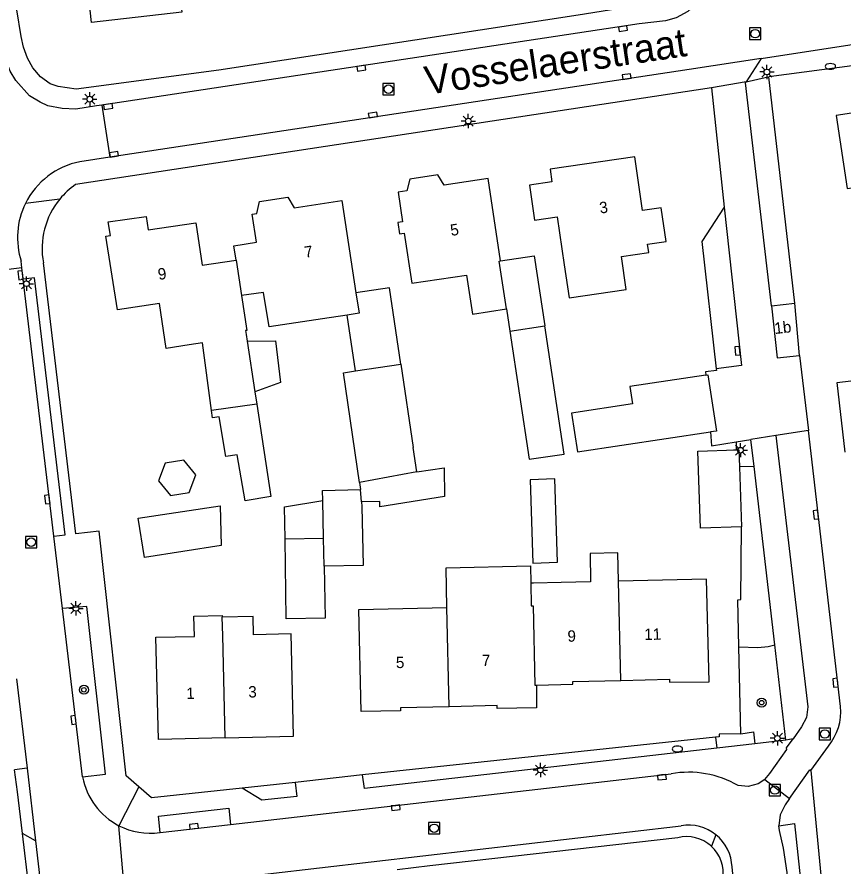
# Model space of a CAD drawing. Extents: x 140000 to 143000, y 403500 to 406000.
# Drawn here: x 140434.8 to 140507.5, y 403776.7 to 403851.4 of the extents above; entities that cross this region are included whole.
import ezdxf

# ---------------------------------------------------------------- set-up
doc = ezdxf.new("R2010")
doc.units = 0
for name, color, linetype in [('gg-afsc-erfafscheiding', 7, 'Continuous'), ('gg-anno-huisnummerreeks BGT', 7, 'Continuous'), ('gg-anno-openbare ruimte label', 7, 'Continuous'), ('gg-bbg-bijgebouw', 7, 'Continuous'), ('gg-bbg-gedigitaliseerde bebouwing', 7, 'Continuous'), ('gg-bbg-gedigitaliseerde bijgebouw', 7, 'Continuous'), ('gg-bbg-hoofdgebouw', 7, 'Continuous'), ('gg-bbg-luifel en loopbrug', 7, 'Continuous'), ('gg-bbg-overig bouwwerk', 7, 'Continuous'), ('gg-bbg-tussenscheiding', 7, 'Continuous'), ('gg-knt-verharding', 7, 'Continuous'), ('gg-knt-verharding nz', 7, 'Continuous'), ('gt-grn-groengrens', 7, 'Continuous'), ('gt-grn-vlakafsluiter', 7, 'Continuous'), ('gt-grn-weggrens', 7, 'Continuous'), ('gt-symb-boom', 7, 'Continuous'), ('gt-symb-brandkraan', 7, 'Continuous'), ('gt-symb-kolk', 7, 'Continuous'), ('gt-symb-lichtmast', 7, 'Continuous'), ('gt-symb-rioolschacht', 7, 'Continuous')]:
    doc.layers.add(name, color=color, linetype=linetype)

# ---------------------------------------------------------------- blocks, each defined once
blk = doc.blocks.new('gt0-KOLK')
at = {"layer": 'gt-symb-kolk'}
blk.add_lwpolyline([(0, 0), (0.375, 0), (0.375, 0.4), (-0.375, 0.4), (-0.375, 0), (0, 0)], dxfattribs=at)
blk = doc.blocks.new('gt0-RS')
at = {"layer": 'gt-symb-rioolschacht'}
blk.add_lwpolyline([(-0.5, -0.5), (0.5, -0.5), (0.5, 0.5), (-0.5, 0.5)], close=True, dxfattribs=at)
blk.add_circle((0, 0), 0.375, dxfattribs=at)
blk = doc.blocks.new('gt0-LMAST')
at = {"layer": 'gt-symb-lichtmast'}
for p, q in [((-0.182, 0.173), (-0.447, 0.438)), ((-0.005, 0.246), (-0.005, 0.621)), ((0.172, 0.173), (0.437, 0.438)), ((-0.255, -0.004), (-0.63, -0.004)), ((-0.182, -0.181), (-0.447, -0.446)), ((-0.005, -0.254), (-0.005, -0.629)), ((0.437, -0.446), (0.172, -0.181)), ((0.245, -0.004), (0.62, -0.004))]:
    blk.add_line(p, q, dxfattribs=at)
blk.add_circle((-0.005, -0.004), 0.25, dxfattribs=at)
blk = doc.blocks.new('gt0-BOOM')
at = {"layer": 'gt-symb-boom'}
for radius in [0.4, 0.2]:
    blk.add_circle((0, 0), radius, dxfattribs=at)
blk = doc.blocks.new('gt0-BR')
at = {"layer": 'gt-symb-brandkraan'}
for centre, radius, start, end in [((-0.244, 0), 0.206, 107.56694, 252.43307), ((0.599, -2.664), 3, 106.89205, 107.56694), ((0, -0.691), 0.938, 73.10799, 106.89205), ((-0.599, -2.664), 3, 72.43309, 73.10799), ((0.244, 0), 0.206, 287.56695, 72.43309), ((0.599, 2.664), 3, 252.43307, 253.10797), ((0, 0.691), 0.938, 253.10797, 286.89206), ((-0.599, 2.664), 3, 286.89206, 287.56695)]:
    blk.add_arc(centre, radius, start, end, dxfattribs=at)

msp = doc.modelspace()

# ---------------------------------------------------------------- linework, layer by layer
at = {"layer": 'gg-afsc-erfafscheiding'}
for p, q in [((140503.231, 403826.221), (140500.938, 403846.136)), ((140492.932, 403779.221), (140471.115, 403776.739)), ((140471.115, 403776.739), (140468.236, 403776.411))]:
    msp.add_line(p, q, dxfattribs=at)
msp.add_arc((140493.716, 403776.097), 3.221, 47.69374, 104.08768, dxfattribs=at)
at = {"layer": 'gg-bbg-bijgebouw'}
for p, q in [((140478.15, 403823.755), (140481.22, 403824.22)), ((140464.589, 403820.269), (140468.559, 403820.85)), ((140468.559, 403820.85), (140469.642, 403813.549)), ((140469.962, 403811.391), (140469.642, 403813.549)), ((140498.076, 403813.323), (140498.3, 403813.33)), ((140498.3, 403813.33), (140498.351, 403811.833)), ((140498.351, 403811.833), (140498.53, 403806.572)), ((140461.76, 403805.569), (140461.695, 403808.881)), ((140458.384, 403805.5), (140461.76, 403805.569))]:
    msp.add_line(p, q, dxfattribs=at)
for points in [[(140478.15, 403823.755), (140479.857, 403812.498), (140482.928, 403812.964), (140481.22, 403824.22)], [(140464.933, 403810.456), (140463.52, 403820.112), (140464.589, 403820.269)], [(140495.404, 403819.9), (140492.045, 403819.386), (140488.717, 403818.896), (140488.942, 403817.368), (140483.589, 403816.556), (140484.099, 403813.143), (140495.811, 403814.905)], [(140495.404, 403819.9), (140495.584, 403819.928), (140496.341, 403814.986), (140495.811, 403814.905)], [(140498.53, 403806.572), (140494.93, 403806.45), (140494.7, 403813.21), (140498.076, 403813.323)], [(140480.182, 403803.367), (140482.349, 403803.44), (140482.102, 403810.768), (140479.935, 403810.695), (140480.182, 403803.367)], [(140461.695, 403808.881), (140461.677, 403809.765), (140465.025, 403809.831)], [(140465.107, 403808.773), (140465.139, 403808.352), (140465.243, 403803.165), (140461.811, 403803.096)], [(140446.006, 403803.855), (140445.464, 403807.318), (140452.663, 403808.404), (140452.755, 403804.911), (140446.006, 403803.855)], [(140461.811, 403803.096), (140461.902, 403798.537), (140458.488, 403798.468), (140458.384, 403805.5)]]:
    msp.add_lwpolyline(points, dxfattribs=at)
at = {"layer": 'gg-bbg-gedigitaliseerde bebouwing'}
msp.add_line((140464.858, 403799.306), (140472.622, 403799.466), dxfattribs=at)
msp.add_lwpolyline([(140472.622, 403799.466), (140472.55, 403802.965), (140479.97, 403803.117), (140480.001, 403801.616)], dxfattribs=at)
at = {"layer": 'gg-bbg-gedigitaliseerde bijgebouw'}
msp.add_line((140464.933, 403810.456), (140465.025, 403809.831), dxfattribs=at)
msp.add_lwpolyline([(140469.962, 403811.391), (140472.365, 403811.741), (140472.392, 403809.232), (140466.724, 403808.32), (140466.725, 403808.785), (140465.107, 403808.773)], dxfattribs=at)
at = {"layer": 'gg-bbg-hoofdgebouw'}
for p, q in [((140501.17, 403825.991), (140503.231, 403826.221)), ((140503.65, 403821.639), (140503.231, 403826.221)), ((140455.05, 403822.895), (140455.726, 403818.438)), ((140455.726, 403818.438), (140455.889, 403817.359)), ((140455.889, 403817.359), (140451.917, 403816.778))]:
    msp.add_line(p, q, dxfattribs=at)
for points in [[(140448.38, 403859.973), (140449.301, 403851.812), (140441.361, 403850.92), (140440.881, 403855.261), (140441.741, 403855.361), (140441.317, 403859.174)], [(140528.15, 403843.84), (140523.65, 403843.181), (140523.74, 403842.571), (140519.79, 403841.97), (140519.39, 403844.641), (140506.88, 403842.742), (140507.84, 403836.301), (140520.353, 403838.182), (140520.336, 403838.291), (140524.286, 403838.886), (140525.215, 403832.729), (140526.239, 403832.883), (140529.709, 403833.407), (140528.326, 403842.664)], [(140490.271, 403831.419), (140491.9, 403831.659), (140491.463, 403834.624), (140489.834, 403834.384), (140489.14, 403839.092), (140481.7, 403838.001), (140481.864, 403836.882), (140479.875, 403836.591), (140480.325, 403833.524), (140482.317, 403833.817), (140482.94, 403829.592), (140483.366, 403826.683), (140488.4, 403827.42), (140487.974, 403830.329), (140490.38, 403830.681), (140490.271, 403831.419)], [(140477.327, 403829.937), (140476.24, 403837.18), (140472.384, 403836.595), (140471.833, 403837.516), (140469.345, 403837.135), (140469.097, 403836.097), (140468.33, 403835.981), (140468.721, 403833.372), (140468.31, 403833.311), (140468.46, 403832.322), (140468.87, 403832.384), (140469.535, 403827.975), (140474.353, 403828.701), (140474.875, 403825.258), (140477.85, 403825.732)], [(140454.064, 403830.012), (140453.87, 403831.28), (140455.857, 403831.584), (140455.481, 403834.041), (140455.881, 403834.102), (140456.132, 403835.153), (140458.62, 403835.534), (140459.175, 403834.607), (140463.38, 403835.252), (140464.619, 403827.139)], [(140451.917, 403816.778), (140451.108, 403822.74), (140449.943, 403822.57), (140447.91, 403822.251), (140447.321, 403826.201), (140443.621, 403825.632), (140442.611, 403832.131), (140443.007, 403832.189), (140442.824, 403833.368), (140446.148, 403833.852), (140446.331, 403832.676), (140450.531, 403833.291), (140451.072, 403829.576), (140454.064, 403830.012)], [(140477.85, 403825.732), (140477.215, 403829.92), (140477.327, 403829.937)], [(140463.845, 403825.178), (140461.68, 403824.85), (140456.994, 403824.139), (140456.486, 403827.179), (140454.536, 403826.897)], [(140454.536, 403826.897), (140455, 403823.837), (140454.91, 403823.823), (140454.961, 403823.485), (140455.05, 403822.895)], [(140464.619, 403827.139), (140464.894, 403825.337), (140463.845, 403825.178)], [(140501.17, 403825.991), (140501.69, 403821.421), (140503.65, 403821.639)], [(140507.668, 403813.118), (140506.95, 403819.26), (140510.09, 403819.628)], [(140487.72, 403801.775), (140487.664, 403804.274), (140485.215, 403804.22), (140485.266, 403801.724), (140482.681, 403801.671), (140480.226, 403801.621), (140480.001, 403801.616)], [(140487.915, 403793.056), (140492.21, 403793.152), (140492.21, 403792.9), (140495.7, 403792.942), (140495.471, 403801.951), (140487.72, 403801.775)], [(140472.818, 403790.743), (140468.53, 403790.642), (140468.53, 403790.391), (140465.06, 403790.31), (140464.858, 403799.306)], [(140453.113, 403787.995), (140447.231, 403787.852), (140447.011, 403796.851), (140450.398, 403796.932), (140450.354, 403798.708), (140452.853, 403798.769), (140452.857, 403798.619)], [(140453.113, 403787.995), (140459.13, 403788.142), (140458.91, 403797.142), (140455.611, 403797.06), (140455.57, 403798.686), (140452.857, 403798.619)], [(140480.5, 403792.632), (140483.69, 403792.712), (140483.69, 403792.961), (140487.915, 403793.056)], [(140480.5, 403792.632), (140480.51, 403790.642), (140477.05, 403790.591), (140477.05, 403790.842), (140472.818, 403790.743)]]:
    msp.add_lwpolyline(points, dxfattribs=at)
at = {"layer": 'gg-bbg-luifel en loopbrug'}
for p, q in [((140464.589, 403820.269), (140463.845, 403825.178)), ((140477.85, 403825.732), (140478.15, 403823.755))]:
    msp.add_line(p, q, dxfattribs=at)
for points in [[(140477.327, 403829.937), (140480.285, 403830.386), (140481.22, 403824.22)], [(140468.559, 403820.85), (140467.561, 403827.576), (140464.619, 403827.139)], [(140455.05, 403822.895), (140457.53, 403822.929), (140457.982, 403819.257), (140455.726, 403818.438)], [(140458.384, 403805.5), (140458.327, 403808.311), (140461.695, 403808.881)]]:
    msp.add_lwpolyline(points, dxfattribs=at)
at = {"layer": 'gg-bbg-overig bouwwerk'}
for points in [[(140455.889, 403817.359), (140457.119, 403809.238), (140454.862, 403808.839), (140454.158, 403812.885), (140453.154, 403812.737), (140452.574, 403816.231), (140452.002, 403816.155), (140451.917, 403816.778)], [(140449.461, 403812.429), (140447.815, 403812.155), (140447.229, 403810.594), (140448.288, 403809.305), (140449.934, 403809.578), (140450.52, 403811.14), (140449.461, 403812.429)]]:
    msp.add_lwpolyline(points, dxfattribs=at)
at = {"layer": 'gg-bbg-tussenscheiding'}
for p, q in [((140454.064, 403830.012), (140454.536, 403826.897)), ((140469.962, 403811.391), (140464.933, 403810.456)), ((140465.107, 403808.773), (140465.025, 403809.831)), ((140461.811, 403803.096), (140461.76, 403805.569)), ((140480.001, 403801.616), (140480.043, 403799.618)), ((140487.915, 403793.056), (140487.72, 403801.775)), ((140472.818, 403790.743), (140472.622, 403799.466))]:
    msp.add_line(p, q, dxfattribs=at)
for points in [[(140480.043, 403799.618), (140480.194, 403799.621), (140480.35, 403792.628), (140480.5, 403792.632)], [(140453.113, 403787.995), (140452.897, 403796.992), (140452.857, 403798.619)]]:
    msp.add_lwpolyline(points, dxfattribs=at)
at = {"layer": 'gg-knt-verharding'}
for p, q in [((140500.27, 403847.752), (140562.382, 403857.344)), ((140500.27, 403847.752), (140498.958, 403845.701)), ((140498.958, 403845.701), (140495.89, 403845.171)), ((140495.89, 403845.171), (140439.951, 403836.65)), ((140495.89, 403845.171), (140497.025, 403834.669)), ((140442.265, 403843.641), (140442.959, 403839.06)), ((140442.959, 403839.06), (140440.331, 403838.662)), ((140438.565, 403835.385), (140435.538, 403834.993)), ((140435.228, 403829.329), (140435.158, 403829.915)), ((140435.228, 403829.329), (140430.557, 403828.746)), ((140435.347, 403828.329), (140435.228, 403829.329)), ((140438.041, 403805.734), (140435.347, 403828.329)), ((140503.65, 403821.639), (140504.421, 403815.028)), ((140501.57, 403814.58), (140499.368, 403814.234)), ((140507.25, 403790.771), (140504.421, 403815.028)), ((140498.069, 403814.03), (140499.368, 403814.234)), ((140499.642, 403811.877), (140499.368, 403814.234)), ((140501.463, 403796.199), (140499.642, 403811.877)), ((140438.798, 403799.381), (140438.041, 403805.734)), ((140440.562, 403784.579), (140438.798, 403799.381)), ((140498.485, 403788.356), (140498.309, 403796.01)), ((140502.44, 403787.791), (140501.463, 403796.199)), ((140434.747, 403793.2), (140435.674, 403785.339)), ((140496.255, 403788.056), (140496.366, 403787.094)), ((140502.44, 403787.791), (140499.712, 403787.478)), ((140503.071, 403787.927), (140502.44, 403787.791)), ((140499.712, 403787.478), (140496.366, 403787.094)), ((140504.65, 403785.132), (140506.18, 403787.271)), ((140435.674, 403785.339), (140434.583, 403785.187)), ((140453.566, 403780.392), (140492.34, 403784.841)), ((140465.2, 403784.761), (140459.27, 403784.082)), ((140445.526, 403783.706), (140443.761, 403780.284)), ((140447.389, 403779.683), (140453.566, 403780.392)), ((140447.781, 403774.981), (140493.232, 403780.279)), ((140436.522, 403768.992), (140435.272, 403779.586)), ((140436.426, 403778.955), (140435.272, 403779.586)), ((140447.348, 403779.678), (140447.389, 403779.683)), ((140496.293, 403779.479), (140495.884, 403778.479)), ((140436.426, 403778.955), (140437.48, 403770.012))]:
    msp.add_line(p, q, dxfattribs=at)
for points in [[(140495.774, 403863.698), (140495.774, 403860.327), (140495.693, 403858.222), (140495.547, 403857.026), (140495.254, 403856.074), (140494.797, 403855.06), (140494.11, 403854.258), (140492.904, 403853.297), (140491.709, 403852.751), (140484.179, 403851.562), (140452.54, 403846.72), (140439.996, 403845.053), (140438.41, 403845.293), (140437.709, 403845.514), (140436.854, 403846.143), (140436.187, 403846.918), (140435.709, 403847.784), (140435.367, 403848.738), (140435.163, 403849.67), (140434.791, 403852.034), (140434.739, 403852.545)], [(140565.886, 403855.822), (140540.142, 403851.975), (140510.264, 403847.369), (140500.938, 403846.136)], [(140496.151, 403855.307), (140495.785, 403854.103), (140495.028, 403852.994), (140493.828, 403851.867), (140492.799, 403851.328), (140491.843, 403851.04), (140489.53, 403850.781), (140442.265, 403843.641)], [(140442.265, 403843.641), (140441.786, 403843.569), (140439.975, 403843.291), (140438.753, 403843.331), (140437.492, 403843.578), (140436.823, 403843.909), (140435.907, 403844.467), (140434.691, 403845.818), (140434.182, 403846.632), (140433.748, 403847.776), (140433.464, 403849.881)], [(140500.27, 403847.752), (140493.94, 403846.782), (140442.959, 403839.06)], [(140498.958, 403845.701), (140500.608, 403846.067), (140500.938, 403846.136)], [(140501.17, 403825.991), (140498.9, 403845.61), (140498.958, 403845.701)], [(140497.025, 403834.669), (140495.04, 403831.66), (140496.31, 403820.452)], [(140445.526, 403783.706), (140444.411, 403784.68), (140442.011, 403806.182), (140439.971, 403805.952), (140437.119, 403829.762)], [(140438.041, 403805.734), (140439.034, 403805.846), (140436.34, 403828.447), (140435.347, 403828.329)], [(140496.31, 403820.452), (140496.33, 403820.3), (140495.38, 403820.2), (140495.404, 403819.9)], [(140495.811, 403814.905), (140495.91, 403813.691), (140498.069, 403814.03)], [(140501.57, 403814.58), (140504.37, 403790.742), (140504.26, 403789.79), (140503.81, 403788.962), (140503.071, 403787.927)], [(140498.309, 403796.01), (140498.213, 403800.152), (140498.469, 403800.165), (140498.53, 403806.572)], [(140440.562, 403784.579), (140442.581, 403784.822), (140440.941, 403799.57), (140438.798, 403799.381)], [(140498.485, 403788.356), (140499.59, 403788.543), (140499.712, 403787.478)], [(140498.485, 403788.356), (140496.579, 403788.342), (140496.582, 403788.11), (140496.255, 403788.056)], [(140500.58, 403784.351), (140501.039, 403784.869), (140502.53, 403786.982), (140502.51, 403787.141), (140503.071, 403787.927)], [(140496.366, 403787.094), (140465.38, 403783.54), (140465.2, 403784.761)], [(140435.272, 403779.586), (140434.839, 403783.249), (140434.583, 403785.187)], [(140502.768, 403782.685), (140504.56, 403785.19), (140504.65, 403785.132)], [(140504.65, 403785.132), (140512.95, 403698.381), (140516.275, 403695.636)], [(140459.27, 403784.082), (140459.42, 403782.852), (140456.34, 403782.512), (140454.611, 403783.582)], [(140500.58, 403784.351), (140500, 403783.973), (140499.134, 403783.733), (140498.239, 403783.802)], [(140454.611, 403783.582), (140446.641, 403782.732), (140445.526, 403783.706)], [(140502.768, 403782.685), (140502.371, 403782.13), (140501.933, 403781.243), (140501.824, 403780.26)], [(140447.389, 403779.683), (140447.236, 403781.134), (140453.425, 403781.82), (140453.566, 403780.392)], [(140501.824, 403780.26), (140503.208, 403780.484), (140504.736, 403766.154)], [(140503.408, 403767.118), (140502.55, 403776.162), (140502.23, 403778.32), (140501.88, 403779.851), (140501.824, 403780.26)], [(140505.662, 403694.866), (140505.21, 403698.888), (140497.71, 403776.65)]]:
    msp.add_lwpolyline(points, dxfattribs=at)
for centre, radius, start, end in [((140441.642, 403831.984), 6.806, 101.10971, 153.75778), ((140443.81, 403831.03), 6.817, 124.47579, 140.29752), ((140441.64, 403831.983), 6.804, 153.74639, 197.69438), ((140443.804, 403831.04), 6.806, 140.33217, 190.82465), ((140502.475, 403790.317), 4.796, 320.5714, 5.43032), ((140493.889, 403776.372), 8.61, 59.65445, 100.36727), ((140446.518, 403785.676), 6.056, 190.43946, 242.91946), ((140446.517, 403785.681), 6.06, 242.94488, 277.87673), ((140493.88, 403776.501), 3.833, 50.98158, 99.72486), ((140493.882, 403776.502), 3.831, 2.21596, 50.99513), ((140493.716, 403776.097), 3.221, 351.30492, 47.69628)]:
    msp.add_arc(centre, radius, start, end, dxfattribs=at)
at = {"layer": 'gg-knt-verharding nz'}
msp.add_line((140435.674, 403785.339), (140436.426, 403778.955), dxfattribs=at)
msp.add_lwpolyline([(140497.025, 403834.669), (140498.53, 403820.732), (140496.31, 403820.452)], dxfattribs=at)
at = {"layer": 'gt-grn-groengrens'}
for p, q in [((140498.069, 403814.03), (140498.076, 403813.323)), ((140499.642, 403811.877), (140498.351, 403811.833))]:
    msp.add_line(p, q, dxfattribs=at)
msp.add_lwpolyline([(140498.309, 403796.01), (140499.963, 403795.943), (140500.879, 403796.028), (140501.463, 403796.199)], dxfattribs=at)
at = {"layer": 'gt-grn-vlakafsluiter'}
for p, q in [((140496.255, 403788.056), (140465.2, 403784.761)), ((140459.27, 403784.082), (140454.611, 403783.582))]:
    msp.add_line(p, q, dxfattribs=at)
at = {"layer": 'gt-grn-weggrens'}
for p, q in [((140504.421, 403815.028), (140501.57, 403814.58)), ((140500.58, 403784.351), (140502.768, 403782.685)), ((140444.344, 403773.66), (140443.761, 403780.284))]:
    msp.add_line(p, q, dxfattribs=at)

# ---------------------------------------------------------------- block references
at = {"layer": 'gt-symb-boom'}
for p in [(140440.679, 403792.233), (140500.314, 403791.095)]:
    msp.add_blockref('gt0-BOOM', p, dxfattribs=at)
at = {"layer": 'gt-symb-brandkraan'}
for p in [(140506.357, 403847.049), (140492.9, 403787.028)]:
    msp.add_blockref('gt0-BR', p, dxfattribs=at)
at = {"layer": 'gt-symb-kolk'}
for p, rotation in [((140488.082, 403850.562), -171.40538754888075), ((140465.063, 403847.085), -171.40538754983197), ((140488.466, 403845.953), 8.610570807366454), ((140442.783, 403843.719), -171.38145051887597), ((140466.135, 403842.57), 8.61057080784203), ((140443.363, 403839.121), 8.610570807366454), ((140435.303, 403828.705), 96.79469842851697), ((140498.378, 403822.056), 96.12008835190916), ((140437.653, 403808.988), 96.79469842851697), ((140505.282, 403807.647), 96.64854682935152), ((140507.001, 403792.867), 96.64053085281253), ((140439.963, 403789.602), 96.79469842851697), ((140491.508, 403784.742), -173.45752055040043), ((140468.091, 403782.059), -173.45752055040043), ((140450.375, 403780.026), 6.550496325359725)]:
    msp.add_blockref('gt0-KOLK', p, dxfattribs=dict(at, rotation=rotation))
at = {"layer": 'gt-symb-lichtmast'}
for p in [(140500.78, 403846.558), (140441.199, 403844.169), (140474.505, 403842.242), (140435.623, 403827.942), (140498.459, 403813.302), (140439.981, 403799.398), (140501.7, 403787.97), (140480.847, 403785.18)]:
    msp.add_blockref('gt0-LMAST', p, dxfattribs=at)
at = {"layer": 'gt-symb-rioolschacht'}
for p in [(140499.734, 403849.923), (140467.475, 403845.044), (140436.044, 403805.209), (140505.877, 403788.345), (140501.464, 403783.416), (140471.49, 403780.052)]:
    msp.add_blockref('gt0-RS', p, dxfattribs=at)

# ---------------------------------------------------------------- texts
at = {"layer": 'gg-anno-huisnummerreeks BGT'}
for s, rotation, p in [('3', 8.3, (140486.11, 403834.1)), ('5', 8.6, (140472.995, 403832.137)), ('7', 8.7, (140460.15, 403830.204)), ('9', 8.3, (140447.264, 403828.265)), ('1b', 6.3, (140501.484, 403823.511)), ('9', 1.2, (140483.236, 403796.452)), ('11', 1.2, (140489.993, 403796.605)), ('5', 1.3, (140468.139, 403794.134)), ('7', 1.3, (140475.709, 403794.312)), ('1', 1.4, (140449.699, 403791.413)), ('3', 1.4, (140455.156, 403791.546))]:
    msp.add_text(s, height=1, rotation=rotation, dxfattribs=at).set_placement(p)
at = {"layer": 'gg-anno-openbare ruimte label'}
msp.add_text('Vosselaerstraat', height=2.5, rotation=8.5, dxfattribs=at).set_placement((140470.858, 403844.539))

doc.saveas('drawing.dxf')
